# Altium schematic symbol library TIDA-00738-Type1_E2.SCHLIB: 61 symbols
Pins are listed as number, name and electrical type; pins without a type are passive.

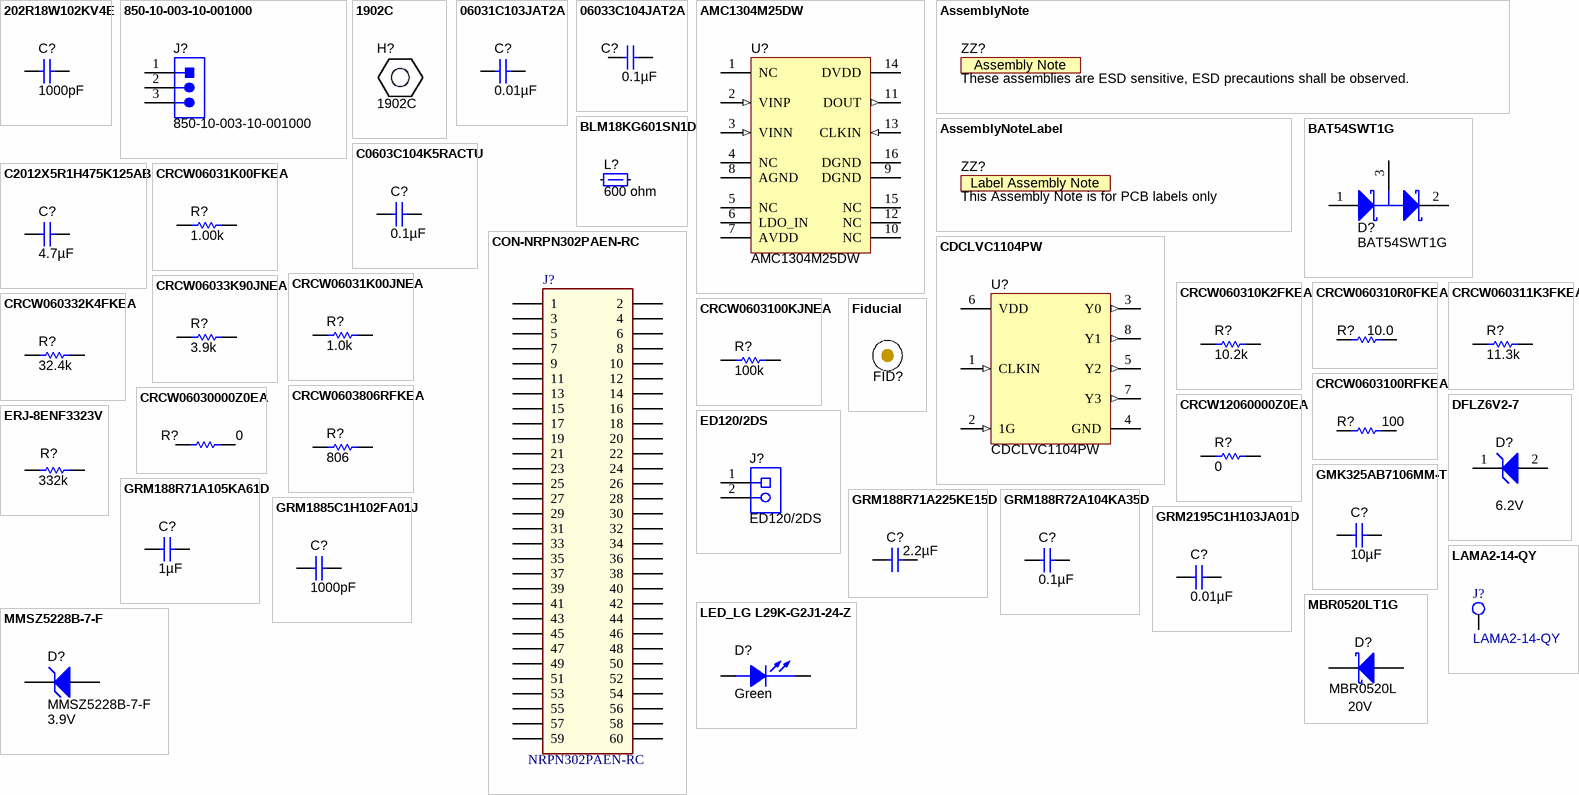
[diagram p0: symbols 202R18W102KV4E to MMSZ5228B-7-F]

## 202R18W102KV4E
designator C?  value 1000pF
CAP CER 1000PF 1KV 10% RADIAL; PartNumber: S102K29Y5PN63J5R; Manufacturer: Vishay BC Components; Polarized: N; CompType: Capacitor; Tolerance_%: 0
signal-integrity model Cap
simulation model Cap
footprint CAP_200mil
footprint 1206M
footprint 1206L
pins: 1, 2

## 850-10-003-10-001000
designator J?
Header, 50mil, 3x1, Gold, TH; Manufacturer: Mill-Max; SymbolCreator: a0799628; U/M: EA
footprint Mill-Max_850-10-003-10-001000
pins: 1, 2, 3
3 alternate drawings of the same symbol

## 1902C
designator H?
Standoff, Hex, 0.5"L #4-40 Nylon; Manufacturer: Keystone; CompType: Hardware
footprint Keystone_1902C

## 06031C103JAT2A
designator C?  ValueDisplayed: 0.01µF
CAP, CERM, 0.01uF, 100V, +/-5%, X7R, 0603; PartNumber: 06031C103J4Z4A; Manufacturer: AVX; Polarized: N; CompType: Capacitor; U/M: EA; Cap_F: 0.00000001; Tolerance_%: 5; ESR_Ohm: 0.098; Value1: 0.098 ohm; VDC_V: 100; TaMin_C: -55; TaMax_C: 125; Cap_Case: 0603
signal-integrity model Cap
simulation model Cap
footprint 0603 (0603 from SM-752 data)
footprint 0603M
footprint 0603L
footprint 0603_HV
pins: 1, 2

## 06033C104JAT2A
designator C?  ValueDisplayed: 0.1µF
CAP, CERM, 0.1uF, 25V, +/-5%, X7R, 0603; PartNumber: 06033C104JAT2A; Manufacturer: AVX; Polarized: N; CompType: Capacitor; U/M: EA; Cap_F: 0.0000001; Tolerance_%: 5; ESR_Ohm: 0.05; Value1: 0.05 ohm; VDC_V: 25; TaMin_C: -55; TaMax_C: 125; Cap_Case: 0603
signal-integrity model Cap
simulation model Cap
footprint 0603 (0603 from SM-752 data)
footprint 0603M
footprint 0603L
footprint 0603_HV
pins: 1, 2

## AMC1304M25DW
designator U?
20 MHz, Isolated Delta-Sigma Modulator, DW0016B; Manufacturer: Texas Instruments; SymbolCreator: a0411947; CompType: IC; U/M: EA
footprint DW0016B_N
footprint DW0016B_M
footprint DW0016B_L
footprint DW0016B_HV
pins: 1 NC, 2 VINP (in), 3 VINN (in), 4 NC, 5 NC, 6 LDO_IN (power), 7 AVDD (power), 8 AGND (power), 9 DGND (power), 10 NC, 11 DOUT (out), 12 NC, 13 CLKIN (in), 14 DVDD (power), 15 NC, 16 DGND (power)

## AssemblyNote
designator ZZ?, comment These assemblies are ESD sensitive, ESD precautions shall be observed.  (no BOM)
SymbolCreator: codlsc; CompType: AssemblyNote
footprint AssemblyNote

## AssemblyNoteLabel
designator ZZ?, comment This Assembly Note is for PCB labels only  (no BOM)
SymbolCreator: a0412235
footprint AssemblyNoteLabel

## BAT54SWT1G
designator D?
Diode, Schottky, 30 V, 0.2 A, SOT-323; Manufacturer: Fairchild Semiconductor; U/M: EA; Vf_V: 0.8; Value: 30V; Value1: 0.2A; Value2: 0.8V; Io_A: 0.2; Vr_V: 30; TJmax_C: 125; AEC Category: Q101
signal-integrity model Diode
footprint SOT-323
pins: 1 A, 2 K, 3 C
2 alternate drawings of the same symbol

## BLM18KG601SN1D
designator L?  value 600 ohm  (hidden comment: BLM18KG601SN1D)
Ferrite Bead, 600 ohm @ 100MHz, 1.3A, 0603; Manufacturer: MuRata; Imax_A: 1.3; DCR_ohm: 0.15; Value1: 0.15 ohm; ZTyp@100MHz_Ohm: 600
footprint 0603
footprint 0603M
footprint 0603L
footprint 0603_HV
footprint 0603S
pins: 1, 2

## C0603C104K5RACTU
designator C?  ValueDisplayed: 0.1µF
CAP, CERM, 0.1uF, 50V, +/-10%, X7R, 0603; PartNumber: C0603C104K5RACTU; Manufacturer: Kemet; Polarized: N; CompType: Capacitor; U/M: EA; Cap_F: 0.0000001; Tolerance_%: 10; Value1: Unknown; VDC_V: 50; TaMin_C: -55; TaMax_C: 125; Cap_Case: 0603
signal-integrity model Cap
simulation model Cap
footprint 0603 (0603 from SM-752 data)
footprint 0603M
footprint 0603L
footprint 0603_HV
pins: 1, 2

## C2012X5R1H475K125AB
designator C?  ValueDisplayed: 4.7µF
CAP, CERM, 4.7uF, 50V, +/-10%, X5R, 0805; PartNumber: C2012X5R1H475K125AB; Manufacturer: TDK; Polarized: N; CompType: Capacitor; U/M: EA; Cap_F: 0.0000047; Tolerance_%: 10; Value1: Unknown; VDC_V: 50; TaMin_C: -55; TaMax_C: 85; Cap_Case: 0805
signal-integrity model Cap
simulation model Cap
footprint 0805_HV (0805 with 30mil clearance between pads)
footprint 0805
footprint 0805M
footprint 0805L
pins: 1, 2

## CDCLVC1104PW
designator U?
3.3 V and 2.5 V LVCMOS High-Performance Clock Buffer; Manufacturer: Texas Instruments; SymbolCreator: a0411947; CompType: IC; U/M: EA
footprint PW0008A_N
footprint PW0008A_M
footprint PW0008A_L
pins: 1 CLKIN (in), 2 1G (in), 3 Y0 (out), 4 GND (power), 5 Y2 (out), 6 VDD (power), 7 Y3 (out), 8 Y1 (out)

## CON-NRPN302PAEN-RC
designator J?, comment NRPN302PAEN-RC
CONN HEADER 2MM DUAL STR 60POS; Manufacturer: Sullins Connector Solutions; CompType: Connector
footprint CONN_NRPN302PAEN-RC
pins: 1, 2, 3, 4, 5, 6, 7, 8, 9, 10, 11, 12, 13, 14, 15, 16, 17, 18, 19, 20, 21, 22, 23, 24, 25, 26, 27, 28, 29, 30, 31, 32, 33, 34, 35, 36, 37, 38, 39, 40, 41, 42, 43, 44, 45, 46, 47, 48, 49, 50, 51, 52, 53, 54, 55, 56, 57, 58, 59, 60

## CRCW06031K00FKEA
designator R?  ValueDisplayed: 1.00k  (hidden comment: CRCW06031K00FKEA)
RES, 1.00 k, 1%, 0.1 W, 0603; Manufacturer: Vishay-Dale; CompType: Resistor; Value: 1.00k; Res_ohm: 1000; Value_Code: 1k00; Tolerance_%: 1; Power_W: 0.1; Value2: 0.1W; VDC_V: 75; TempCo: 100 ppm/C; EIA_Code: E96; U/M: EA; AEC Category: Q200
signal-integrity model Resistor
simulation model Resistor
footprint 0603
footprint 0603M
footprint 0603L
footprint 0603_HV
footprint 0603S
pins: 1, 2

## CRCW06031K00JNEA
designator R?  value 1.0k  (hidden comment: CRCW06031K00JNEA)
RES, 1.0k ohm, 5%, 0.1W, 0603; Manufacturer: Vishay-Dale; CompType: Resistor; Res_ohm: 1000; Value_Code: 1k00; Tolerance_%: 5; Power_W: 0.1; VDC_V: 75; TempCo: 200 ppm/C; EIA_Code: E24; U/M: EA
signal-integrity model Resistor
simulation model Resistor
footprint 0603
footprint 0603M
footprint 0603L
footprint 0603_HV
footprint 0603S
pins: 1, 2

## CRCW06033K90JNEA
designator R?  value 3.9k
RES, 3.9k ohm, 5%, 0.1W, 0603; PartNumber: CRCW06033K90JNEA; Manufacturer: Vishay-Dale; CompType: Resistor; Res_ohm: 3900; Value_Code: 3k90; Tolerance_%: 5; Power_W: 0.1; VDC_V: 75; TempCo: 200 ppm/C; EIA_Code: E24; U/M: EA
signal-integrity model Resistor
simulation model Resistor
footprint 0603 (0603 from SM-752 data)
footprint 0603M
footprint 0603L
footprint 0603_HV
footprint 0603
footprint 0603_HV
footprint 0603L
footprint 0603M
simulation model Resistor
signal-integrity model Resistor
pins: 1, 2

## CRCW060310K2FKEA
designator R?  ValueDisplayed: 10.2k  (hidden comment: CRCW060310K2FKEA)
RES, 10.2 k, 1%, 0.1 W, 0603; Manufacturer: Vishay-Dale; CompType: Resistor; Value: 10.2k; Res_ohm: 10200; Value_Code: 10k2; Tolerance_%: 1; Power_W: 0.1; Value2: 0.1W; VDC_V: 75; TempCo: 100 ppm/C; EIA_Code: E96; U/M: EA
signal-integrity model Resistor
simulation model Resistor
footprint 0603
footprint 0603M
footprint 0603L
footprint 0603_HV
footprint 0603S
pins: 1, 2

## CRCW060310R0FKEA
designator R?  value 10.0
RES, 10.0 ohm, 1%, 0.1W, 0603; PartNumber: CRCW060310R0FKEA; Manufacturer: Vishay-Dale; CompType: Resistor; Res_ohm: 10; Value_Code: 10R0; Tolerance_%: 1; Power_W: 0.1; VDC_V: 75; TempCo: 100 ppm/C; EIA_Code: E96; U/M: EA
signal-integrity model Resistor
simulation model Resistor
footprint 0603 (0603 from SM-752 data)
footprint 0603M
footprint 0603L
footprint 0603_HV
pins: 1, 2

## CRCW060311K3FKEA
designator R?  ValueDisplayed: 11.3k  (hidden comment: CRCW060311K3FKEA)
RES, 11.3 k, 1%, 0.1 W, 0603; Manufacturer: Vishay-Dale; CompType: Resistor; Value: 11.3k; Res_ohm: 11300; Value_Code: 11k3; Tolerance_%: 1; Power_W: 0.1; Value2: 0.1W; VDC_V: 75; TempCo: 100 ppm/C; EIA_Code: E96; U/M: EA
signal-integrity model Resistor
simulation model Resistor
footprint 0603
footprint 0603M
footprint 0603L
footprint 0603_HV
footprint 0603S
pins: 1, 2

## CRCW060332K4FKEA
designator R?  ValueDisplayed: 32.4k  (hidden comment: CRCW060332K4FKEA)
RES, 32.4 k, 1%, 0.1 W, 0603; Manufacturer: Vishay-Dale; CompType: Resistor; Value: 32.4k; Res_ohm: 32400; Value_Code: 32k4; Tolerance_%: 1; Power_W: 0.1; Value2: 0.1W; VDC_V: 75; TempCo: 100 ppm/C; EIA_Code: E96; U/M: EA; AEC Category: Q200
signal-integrity model Resistor
simulation model Resistor
footprint 0603
footprint 0603M
footprint 0603L
footprint 0603_HV
footprint 0603S
pins: 1, 2

## CRCW0603100KJNEA
designator R?  ValueDisplayed: 100k  (hidden comment: CRCW0603100KJNEA)
RES, 100 k, 5%, 0.1 W, 0603; Manufacturer: Vishay-Dale; CompType: Resistor; Value: 100k; Res_ohm: 100000; Tolerance_%: 5; Power_W: 0.1; Value2: 0.1W; VDC_V: 75; TempCo: 200 ppm/C; EIA_Code: E24; U/M: EA; AEC Category: Q200
signal-integrity model Resistor
simulation model Resistor
footprint 0603
footprint 0603M
footprint 0603L
footprint 0603_HV
footprint 0603S
pins: 1, 2

## CRCW0603100RFKEA
designator R?  ValueDisplayed: 100  (hidden comment: CRCW0603100RFKEA)
RES, 100, 1%, 0.1 W, 0603; Manufacturer: Vishay-Dale; CompType: Resistor; Value: 100; Value_Code: 100R; Tolerance_%: 1; Power_W: 0.1; Value2: 0.1W; VDC_V: 75; TempCo: 100 ppm/C; EIA_Code: E96; U/M: EA
signal-integrity model Resistor
simulation model Resistor
footprint 0603
footprint 0603M
footprint 0603L
footprint 0603_HV
footprint 0603S
pins: 1, 2

## CRCW0603806RFKEA
designator R?  ValueDisplayed: 806  (hidden comment: CRCW0603806RFKEA)
RES, 806, 1%, 0.1 W, 0603; Manufacturer: Vishay-Dale; CompType: Resistor; Value: 806; Value_Code: 806R; Tolerance_%: 1; Power_W: 0.1; Value2: 0.1W; VDC_V: 75; TempCo: 100 ppm/C; EIA_Code: E96; U/M: EA; AEC Category: Q200
signal-integrity model Resistor
simulation model Resistor
footprint 0603
footprint 0603M
footprint 0603L
footprint 0603_HV
footprint 0603S
pins: 1, 2

## CRCW06030000Z0EA
designator R?  ValueDisplayed: 0  (hidden comment: CRCW06030000Z0EA)
RES, 0, 5%, 0.1 W, 0603; Manufacturer: Vishay-Dale; CompType: Resistor; Value: 0; Value_Code: 0000; Tolerance_%: 5; Power_W: 0.1; Value2: 0.1W; VDC_V: 75; TempCo: 200 ppm/C; EIA_Code: E24; U/M: EA; AEC Category: Q200
signal-integrity model Resistor
simulation model Resistor
footprint 0603
footprint 0603M
footprint 0603L
footprint 0603_HV
footprint 0603S
pins: 1, 2

## CRCW12060000Z0EA
designator R?  ValueDisplayed: 0  (hidden comment: CRCW12060000Z0EA)
RES, 0, 5%, 0.25 W, 1206; Manufacturer: Vishay-Dale; CompType: Resistor; Value: 0; Value_Code: 0000; Tolerance_%: 5; Power_W: 0.25; Value2: 0.25W; VDC_V: 200; TempCo: 200 ppm/C; EIA_Code: E24; U/M: EA
signal-integrity model Resistor
simulation model Resistor
footprint 1206
footprint 1206M
footprint 1206L
pins: 1, 2

## DFLZ6V2-7
designator D?  value 6.2V
Diode, Zener, 6.2V, 1W, PowerDI123; PartNumber: DFLZ6V2-7; Manufacturer: Diodes Inc.; U/M: EA; Power_W: 1; Vz_V: 6.2; RJA_CperW: 110
signal-integrity model Diode
footprint powerDI123 (Diodes Inc recommended land pattern, document number DS30628 Rev. 6-2)
pins: 1 K, 2 A

## ED120/2DS
designator J?
TERMINAL BLOCK 5.08MM VERT 2POS, TH; Manufacturer: On-Shore Technology; SymbolCreator: a0412235; U/M: EA
footprint CONN_ED120-2DS (ONSHORE)
pins: 1, 2

## ERJ-8ENF3323V
designator R?  ValueDisplayed: 332k  (hidden comment: ERJ-8ENF3323V)
RES, 332 k, 1%, 0.25 W, 1206; Manufacturer: Panasonic; CompType: Resistor; Value: 332k; Res_ohm: 332000; Tolerance_%: 1; Power_W: 0.25; Value2: 0.25W; VDC_V: 200; TempCo: 100 ppm/C; EIA_Code: E96; U/M: EA
signal-integrity model Resistor
simulation model Resistor
footprint 1206 (1206 from SM-752 data)
footprint 1206M
footprint 1206L
pins: 1, 2

## Fiducial
designator FID?  (value not drawn)
Fiducial mark.  There is nothing to buy or mount.; SymbolCreator: codlsc
footprint Fiducial10-30
footprint Fiducial10-20
footprint Fiducial15-30
footprint Fiducial20-40
footprint Fiducial6.4-20
footprint Fiducial10-30_TopLayerKeepOutOnly
footprint Fiducial6.4-20_TopLayerKeepOutOnly
footprint Fiducial10-20_TopLayerKeepOutOnly
footprint Fiducial15-30_TopLayerKeepOutOnly
footprint Fiducial20-40_TopLayerKeepOutOnly

## GMK325AB7106MM-T
designator C?  ValueDisplayed: 10µF
CAP, CERM, 10uF, 35V, +/-20%, X7R, 1210; PartNumber: GMK325AB7106MM-T; Manufacturer: Taiyo Yuden; Polarized: N; CompType: Capacitor; U/M: EA; Cap_F: 0.00001; Tolerance_%: 20; Value1: Unknown; VDC_V: 35; TaMin_C: -55; TaMax_C: 125; Cap_Case: 1210
signal-integrity model Cap
simulation model Cap
footprint 1210 (1210 from SM-752 data)
footprint 1210M
footprint 1210L
pins: 1, 2

## GRM188R71A105KA61D
designator C?  ValueDisplayed: 1µF  (hidden comment: GRM188R71A105KA61D)
CAP, CERM, 1uF, 10V, +/-10%, X7R, 0603; Manufacturer: MuRata; Polarized: N; CompType: Capacitor; U/M: EA; Cap_F: 0.000001; Tolerance_%: 10; ESR_Ohm: 0.011; Value1: 0.011 ohm; TaMin_C: -55; TaMax_C: 125; Cap_Case: 0603
signal-integrity model Cap
simulation model Cap
footprint 0603
footprint 0603M
footprint 0603L
footprint 0603_HV
footprint 0603S
pins: 1, 2

## GRM188R71A225KE15D
designator C?  ValueDisplayed: 2.2µF  (hidden comment: GRM188R71A225KE15D)
CAP, CERM, 2.2 µF, 10 V, +/- 10%, X7R, 0603; Manufacturer: MuRata; Polarized: N; CompType: Capacitor; Value: 2.2uF; U/M: EA; Cap_F: 0.0000022; Tolerance_%: 10; ESR_ohm: 0.009; Value1: 0.009 ohm; Value2: 10V; TaMin_C: -55; TaMax_C: 125; Cap_Case: 0603; AEC Category: Q200
signal-integrity model Cap
simulation model Cap
footprint 0603
footprint 0603M
footprint 0603L
footprint 0603_HV
footprint 0603S
pins: 1, 2

## GRM188R72A104KA35D
designator C?  ValueDisplayed: 0.1µF  (hidden comment: GRM188R72A104KA35D)
CAP, CERM, 0.1 µF, 100 V, +/- 10%, X7R, 0603; Manufacturer: MuRata; Polarized: N; CompType: Capacitor; Value: 0.1uF; U/M: EA; Cap_F: 0.0000001; Tolerance_%: 10; Value1: Unknown; VDC_V: 100; Value2: 100V; TaMin_C: -55; TaMax_C: 125; Cap_Case: 0603; AEC Category: Q200
signal-integrity model Cap
simulation model Cap
footprint 0603
footprint 0603M
footprint 0603L
footprint 0603_HV
footprint 0603S
pins: 1, 2

## GRM1885C1H102FA01J
designator C?  ValueDisplayed: 1000pF  (hidden comment: GRM1885C1H102FA01J)
CAP, CERM, 1000 pF, 50 V, +/- 1%, C0G/NP0, 0603; Manufacturer: MuRata; Polarized: N; CompType: Capacitor; Value: 1000pF; U/M: EA; Cap_F: 0.000000001; Tolerance_%: 1; Value1: Unknown; VDC_V: 50; Value2: 50V; TaMin_C: -55; TaMax_C: 125; Cap_Case: 0603; AEC Category: Q200
signal-integrity model Cap
simulation model Cap
footprint 0603
footprint 0603M
footprint 0603L
footprint 0603_HV
footprint 0603S
pins: 1, 2

## GRM2195C1H103JA01D
designator C?  ValueDisplayed: 0.01µF  (hidden comment: GRM2195C1H103JA01D)
CAP, CERM, 0.01 µF, 50 V, +/- 5%, C0G/NP0, 0805; Manufacturer: MuRata; Polarized: N; CompType: Capacitor; Value: 0.01uF; U/M: EA; Cap_F: 0.00000001; Tolerance_%: 5; Value1: Unknown; VDC_V: 50; Value2: 50V; TaMin_C: -55; TaMax_C: 125; Cap_Case: 0805; AEC Category: Q200
signal-integrity model Cap
simulation model Cap
footprint 0805_HV
footprint 0805_HV1
footprint 0805
footprint 0805M
footprint 0805L
pins: 1, 2

## LAMA2-14-QY
designator J?
MECHANICAL LUG ALUM 2-14 AWG; Manufacturer: Panduit Corp
footprint PANDUIT_LAMA2-14-QY (MECHANICAL LUG ALUM 2-14 AWG,TH)
pins: 1

## LED_LG L29K-G2J1-24-Z
designator D?  value Green
LED SmartLED Green 570NM; PartNumber: LG L29K-G2J1-24-Z; Manufacturer: OSRAM; SymbolCreator: x0120606
footprint LED0603AA
pins: 1 C, 2 A

## MBR0520LT1G
designator D?, comment MBR0520L  value 20V
Diode, Schottky, 20V, 0.5A, SOD-123; Manufacturer: Fairchild Semiconductor; U/M: EA; Vf_V: 0.385; Value2: 0.385V; Io_A: 0.5; Vr_V: 20; TJmax_C: 125; RJC_CperW: 150
signal-integrity model Diode
simulation model mbr0520lt1
footprint SOD-123 (On Semi recommended land pattern)
pins: 1 K, 2 A

## MMSZ5228B-7-F
designator D?  value 3.9V
Diode, Zener, 3.9 V, 500 mW, SOD-123; Manufacturer: Diodes Inc.; SymbolCreator: a0412235; U/M: EA; Power_W: 0.5; Vz_V: 3.9; Value1: 0.5W; RJA_CperW: 350; AEC Category: AEC-Q101
signal-integrity model Diode
footprint SOD-123
pins: 1 K, 2 A

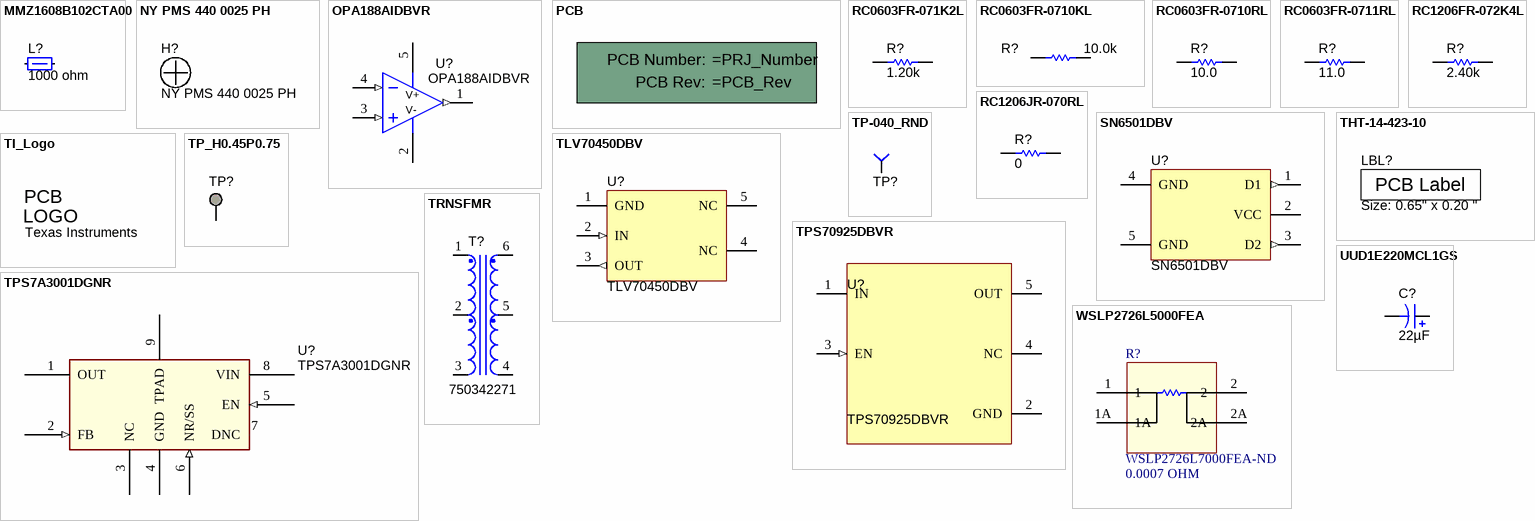
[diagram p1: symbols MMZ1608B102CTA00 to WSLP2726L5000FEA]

## MMZ1608B102CTA00
designator L?  value 1000 ohm  (hidden comment: MMZ1608B102CTA00)
Ferrite Bead, 1000 ohm @ 100 MHz, 0.3 A, 0603; Manufacturer: TDK; Imax_A: 0.3; DCR_ohm: 0.6; Value1: 0.6 ohm; Value2: 0.3A; ZTyp@100MHz_Ohm: 1000
footprint MMZ1608_095 (TDK)
pins: 1, 2

## NY PMS 440 0025 PH
designator H?
Machine Screw, Round, #4-40 x 1/4, Nylon, Philips panhead; Manufacturer: B&F Fastener Supply; CompType: Hardware; SymbolCreator: codlsc; U/M: EA
footprint NY PMS 440 0025 PH

## OPA188AIDBVR
designator U?
Precision, Low-Noise, Rail-to-Rail Output, 36 V, Zero-Drift Operational Amplifiers, DBV0005A; Alternate PartNumber: OPA188AIDBVT; Manufacturer: Texas Instruments; CompType: IC; U/M: EA
footprint DBV0005A_N
footprint DBV0005A_M
footprint DBV0005A_L
pins: 1 OUT (out), 2 V- (power), 3 IN+ (in), 4 IN- (in), 5 V+ (power)
1 alternate drawing of the same symbol

## PCB
designator !PCB?, comment Printed Circuit Board  (value not drawn)  (mechanical)
Manufacturer: Any; SymbolCreator: a0412235; CompType: PCB
1 alternate drawing of the same symbol

## RC0603FR-071K2L
designator R?  ValueDisplayed: 1.20k  (hidden comment: RC0603FR-071K2L)
RES, 1.20 k, 1%, 0.1 W, 0603; Manufacturer: Yageo America; CompType: Resistor; Value: 1.20k; Res_ohm: 1200; Value_Code: 1k20; Tolerance_%: 1; Power_W: 0.1; Value2: 0.1W; VDC_V: 150; TempCo: 200 ppm/C; U/M: EA; AEC Category: Q200
signal-integrity model Resistor
simulation model Resistor
footprint 0603
footprint 0603M
footprint 0603L
footprint 0603_HV
footprint 0603S
pins: 1, 2

## RC0603FR-0710KL
designator R?  ValueDisplayed: 10.0k  (hidden comment: RC0603FR-0710KL)
RES, 10.0 k, 1%, 0.1 W, 0603; Manufacturer: Yageo America; CompType: Resistor; Value: 10.0k; Res_ohm: 10000; Value_Code: 10k0; Tolerance_%: 1; Power_W: 0.1; Value2: 0.1W; VDC_V: 150; TempCo: 200 ppm/C; EIA_Code: E96; U/M: EA; AEC Category: Q200
signal-integrity model Resistor
simulation model Resistor
footprint 0603
footprint 0603M
footprint 0603L
footprint 0603_HV
footprint 0603S
pins: 1, 2

## RC0603FR-0710RL
designator R?  ValueDisplayed: 10.0  (hidden comment: RC0603FR-0710RL)
RES, 10.0, 1%, 0.1 W, 0603; Manufacturer: Yageo America; CompType: Resistor; Value: 10.0; Res_ohm: 10; Value_Code: 10R0; Tolerance_%: 1; Power_W: 0.1; Value2: 0.1W; VDC_V: 150; TempCo: 200 ppm/C; EIA_Code: E96; U/M: EA; AEC Category: Q200
signal-integrity model Resistor
simulation model Resistor
footprint 0603
footprint 0603M
footprint 0603L
footprint 0603_HV
footprint 0603S
pins: 1, 2

## RC0603FR-0711RL
designator R?  ValueDisplayed: 11.0  (hidden comment: RC0603FR-0711RL)
RES, 11.0, 1%, 0.1 W, 0603; Manufacturer: Yageo America; CompType: Resistor; Value: 11.0; Res_ohm: 11; Value_Code: 11R0; Tolerance_%: 1; Power_W: 0.1; Value2: 0.1W; VDC_V: 150; TempCo: 200 ppm/C; EIA_Code: E96; U/M: EA; AEC Category: Q200
signal-integrity model Resistor
simulation model Resistor
footprint 0603
footprint 0603M
footprint 0603L
footprint 0603_HV
footprint 0603S
pins: 1, 2

## RC1206FR-072K4L
designator R?  ValueDisplayed: 2.40k  (hidden comment: RC1206FR-072K4L)
RES, 2.40 k, 1%, 0.25 W, 1206; Manufacturer: Yageo America; CompType: Resistor; Value: 2.40k; Res_ohm: 2400; Value_Code: 2k40; Tolerance_%: 1; Power_W: 0.25; Value2: 0.25W; VDC_V: 200; TempCo: 100 ppm/C; U/M: EA
signal-integrity model Resistor
simulation model Resistor
footprint 1206 (1206 from SM-752 data)
footprint 1206M
footprint 1206L
pins: 1, 2

## RC1206JR-070RL
designator R?  ValueDisplayed: 0  (hidden comment: RC1206JR-070RL)
RES, 0, 5%, 0.25 W, 1206; Manufacturer: Yageo America; CompType: Resistor; Value: 0; Value_Code: 0000; Tolerance_%: 5; Power_W: 0.25; Value2: 0.25W; VDC_V: 200; TempCo: 200 ppm/C; EIA_Code: E24; U/M: EA; AEC Category: Q200
signal-integrity model Resistor
simulation model Resistor
footprint 1206
footprint 1206M
footprint 1206L
pins: 1, 2

## SN6501DBV
designator U?
Transformer Driver for Isolated Power Supplies, DBV0005A; Alternate Manufacturer: None; Manufacturer: Texas Instruments; SymbolCreator: a0411947; CompType: IC; U/M: EA
footprint DBV0005A_N (SOT23, 5-Leads, Body 2.9x1.6mm, Pitch 0.95mm, Lead Span 2.8mm, IPC Medium Density)
footprint DBV0005A_M
footprint DBV0005A_L
pins: 1 D1 (out), 2 VCC (power), 3 D2 (out), 4 GND (power), 5 GND (power)

## THT-14-423-10
designator LBL?, comment Size: 0.65" x 0.20 "
Thermal Transfer Printable Labels, 0.650" W x 0.200" H - 10,000 per roll; Manufacturer: Brady; PartNumber: THT-14-423-10; SymbolCreator: a0412235; CompType: Label
footprint Label_650x200

## TI_Logo
designator Logo?, comment Texas Instruments  (no BOM)
Texas Instrument Corporate Signature; SymbolCreator: codlsc
footprint TI_Stacked_SolderMask_Medium
footprint TI_Stacked_SolderMask_Small
footprint TI_Stacked_Overlay_Medium
footprint TI_Stacked_Overlay_Small
footprint TI_Horizontal_SolderMask_Medium
footprint TI_Horizontal_SolderMask_Small
footprint TI_Horizontal_Overlay_Medium
footprint TI_Horizontal_Overlay_Small
footprint TI_Symbol_SolderMask_Small
footprint TI_Symbol_Overlay_Medium
footprint TI_Symbol_Overlay_Small
footprint TI_Symbol_SolderMask_Medium

## TLV70450DBV
designator U?
Regulator, LDO, 5V, 0.15A, SOT23-5; Alternate Manufacturer: None; Manufacturer: Texas Instruments; SymbolCreator: x0120606; CompType: IC
footprint DBV0005A_N (SOT23, 5-Leads, Body 2.9x1.6mm, Pitch 0.95mm, Lead Span 2.8mm, IPC Medium Density)
pins: 1 GND (power), 2 IN (in), 3 OUT (out), 4 NC (power), 5 NC (power)
1 alternate drawing of the same symbol

## TP-040_RND
designator TP?
Test Point, O.040 Hole; Manufacturer: STD; Value: STD
footprint TP-040_RND
pins: 1

## TP_H0.45P0.75
designator TP?, comment TESTPOINT  (value not drawn)  (no BOM)
Manufacturer: Texas Instruments; PartNumber: TP_H0.45P0.75; CompType: Pad
footprint TP_H045P075
pins: 1

## TPS7A3001DGNR
designator U?
-36V, -200mA, Ultralow-Noise, Negative Linear Regulator; Alternate Manufacturer: None; Manufacturer: Texas Instruments; CompType: IC; SymbolCreator: x0120606
footprint DGN0008D_N (TSOP, 8-Leads, Body 3x3mm, Pitch 0.65mm, Thermal Pad 1.89x1.57mm, IPC Medium Density)
pins: 1 OUT (power), 2 FB (in), 3 NC, 4 GND (power), 5 EN (in), 6 NR/SS (in), 7 DNC, 8 VIN (power), 9 TPAD

## TPS70925DBVR
designator U?
150-mA, 30-V, 1-µA IQ Voltage Regulator with Enable, DBV0005A; Alternate PartNumber: TPS70925DBVT; Manufacturer: Texas Instruments; SymbolCreator: Altium; CompType: IC; U/M: EA
footprint DBV0005A_N
footprint DBV0005A_M
footprint DBV0005A_L
pins: 1 IN (power) "Unregulated input to the device", 2 GND (power) "Ground", 3 EN (in) "Enable pin", 4 NC "No internal connection", 5 OUT (power) "Regulated output voltage."
1 alternate drawing of the same symbol

## TRNSFMR
designator T?, comment 750342271
Transformer 469uH SMD; Manufacturer: Wurth Electronics Midcom
footprint 760390015
pins: 1, 2, 3, 4, 5, 6

## UUD1E220MCL1GS
designator C?  ValueDisplayed: 22µF  (hidden comment: UUD1E220MCL1GS)
CAP, AL, 22uF, 25V, +/-20%, 0.76 ohm, SMD; Manufacturer: Nichicon; Polarized: Y; CompType: Capacitor; U/M: EA; Cap_F: 0.000022; Tolerance_%: 20; VDC_V: 25; ESR_Ohm: 0.76; IRMS_A: 0.15; TaMin_C: -55; TaMax_C: 105; Cap_Case: 5x5.8
signal-integrity model Cap
simulation model Cap
footprint SM_RADIAL_5MM (Nichicon 5x5.8)
pins: 1 +, 2 -

## WSLP2726L5000FEA
designator R?, comment WSLP2726L7000FEA-ND  value 0.0007 OHM
RES SMD 0.0007 OHM 1% 7W 2726; Manufacturer: VISHAY; CompType: RESISTOR; SymbolCreator: x0199378
footprint RES_WSLP2726
pins: 1, 1A, 2, 2A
